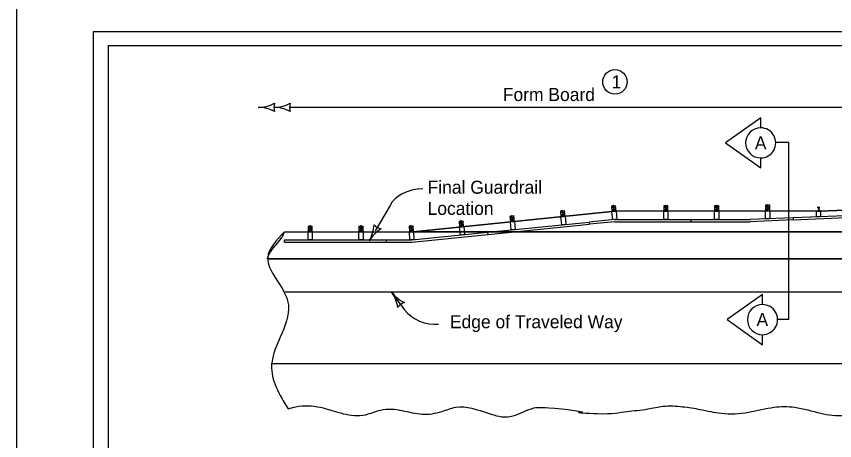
# Model space of a CAD drawing. Extents: x 10038 to 81668, y 7924 to 11018.
# Drawn here: x 10038 to 11041, y 9442 to 9962 of the extents above; entities that cross this region are included whole.
import ezdxf

# ---------------------------------------------------------------- set-up
doc = ezdxf.new("R2010")
doc.units = 0
for name, color, linetype in [('dsnCellElements', 7, 'Continuous'), ('DsnShtMinorGrid05', 7, 'Continuous'), ('DsnShtMinorGrid06', 7, 'Continuous'), ('DsnShtMinorGrid07', 7, 'Continuous'), ('DsnShtMinorGrid09', 7, 'Continuous'), ('DsnShtMinorGrid10', 7, 'Continuous'), ('DsnShtMinorGrid11', 7, 'Continuous'), ('DsnShtMinorGrid13', 7, 'Continuous'), ('DsnShtMinorGrid14', 7, 'Continuous'), ('Level 60', 7, 'Continuous'), ('SheetBorder', 7, 'Continuous')]:
    doc.layers.add(name, color=color, linetype=linetype)

msp = doc.modelspace()

# ---------------------------------------------------------------- linework, layer by layer
at = {"layer": 'dsnCellElements'}
msp.add_lwpolyline([(10037.7, 8180), (13358.6, 8180), (13358.6, 10373.4), (10037.7, 10373.4)], close=True, dxfattribs=at)
at = {"layer": 'DsnShtMinorGrid05'}
msp.add_line((10373.6, 9850.8), (11396, 9850.8), dxfattribs=at)
for centre, radius, start, end in [((10334.4, 9893.2), 42.5, 270, 298.0725), ((10334.4, 9808.2), 42.5, 61.9275, 90), ((10353.6, 9893.2), 42.5, 270, 298.0725), ((10370, 9850.7), 16.4, 162.2666, 197.7334), ((10353.6, 9808.2), 42.5, 61.9275, 90), ((10389.2, 9850.7), 16.4, 162.2666, 197.7334)]:
    msp.add_arc(centre, radius, start, end, dxfattribs=at)
at = {"layer": 'DsnShtMinorGrid06'}
for q in [(10150.3, 8316.7), (13246, 9926.7)]:
    msp.add_line((10150.3, 9926.7), q, dxfattribs=at)
at = {"layer": 'DsnShtMinorGrid07'}
for p, q in [((11023.5, 9728), (11020.2, 9728)), ((11020.2, 9728), (11020.2, 9727.8)), ((11020.2, 9728), (11020.2, 9727.8)), ((11023.5, 9728), (11020.2, 9728)), ((11020.2, 9727.8), (11021.3, 9727.8)), ((11020.2, 9727.8), (11021.3, 9727.8)), ((11021.8, 9727.4), (11021.8, 9723.6)), ((11021.8, 9727.4), (11021.8, 9723.6)), ((11021.9, 9723.6), (11021.9, 9727.4)), ((11021.9, 9723.6), (11021.9, 9727.4)), ((11022.3, 9727.8), (11023.5, 9727.8)), ((11022.3, 9727.8), (11023.5, 9727.8)), ((11023.5, 9727.8), (11023.5, 9728)), ((11023.5, 9727.8), (11023.5, 9728)), ((11019.2, 9716.4), (11019.2, 9723.4)), ((11019.2, 9723.4), (11019.9, 9723.4)), ((11019.9, 9723.1), (11019.9, 9723.4)), ((11023.6, 9723.1), (11019.9, 9723.1)), ((11021.3, 9723.2), (11020.2, 9723.2)), ((11020.2, 9723.2), (11020.2, 9723.1)), ((11020.2, 9723.2), (11020.2, 9723.1)), ((11021.3, 9723.2), (11020.2, 9723.2)), ((11020.2, 9723.1), (11023.5, 9723.1)), ((11020.2, 9723.1), (11023.5, 9723.1)), ((11022.1, 9723.7), (11022.1, 9723.3)), ((11022.1, 9723.3), (11022.1, 9723.7)), ((11022.2, 9723.7), (11022.1, 9723.7)), ((11022.2, 9723.7), (11022.1, 9723.7)), ((11022.2, 9723.7), (11023.1, 9723.7)), ((11023.1, 9723.7), (11022.2, 9723.7)), ((11023.5, 9723.2), (11022.3, 9723.2)), ((11023.5, 9723.2), (11022.3, 9723.2)), ((11022.9, 9725.2), (11022.4, 9725.2)), ((11022.4, 9725.2), (11022.4, 9723.7)), ((11022.9, 9725.2), (11022.4, 9725.2)), ((11022.4, 9725.2), (11022.4, 9723.7)), ((11022.4, 9723.7), (11022.9, 9723.7)), ((11022.4, 9723.7), (11022.4, 9723.3)), ((11022.4, 9723.3), (11022.4, 9723.7)), ((11022.4, 9723.3), (11022.4, 9723.7)), ((11022.9, 9723.7), (11022.9, 9725.2)), ((11022.9, 9723.7), (11022.9, 9725.2)), ((11023, 9723.3), (11023, 9723.7)), ((11023, 9723.7), (11023, 9723.3)), ((11023, 9723.3), (11023, 9723.7)), ((11023.1, 9723.7), (11023.2, 9723.7)), ((11023.2, 9723.7), (11023.1, 9723.7)), ((11023.3, 9723.7), (11023.2, 9723.7)), ((11023.3, 9723.7), (11023.2, 9723.7)), ((11023.2, 9723.2), (11023.3, 9723.3)), ((11023.2, 9723.2), (11023.3, 9723.3)), ((11023.3, 9723.3), (11023.3, 9723.7)), ((11023.3, 9723.3), (11023.3, 9723.7)), ((11023.5, 9723.1), (11023.5, 9723.2)), ((11023.5, 9723.1), (11023.5, 9723.2)), ((11023.6, 9723.4), (11024.2, 9723.4)), ((11023.6, 9723.4), (11023.6, 9723.1)), ((11024.2, 9723.4), (11024.2, 9716.4)), ((11024.2, 9716.4), (11019.2, 9716.4))]:
    msp.add_line(p, q, dxfattribs=at)
for points in [[(11022.1, 9723.3), (11022.1, 9723.3)], [(11022.3, 9723.2), (11023.2, 9723.2), (11023.2, 9723.2)]]:
    msp.add_lwpolyline(points, dxfattribs=at)
for centre, start, end in [((11021.3, 9727.4), 359.9934, 90.0025), ((11021.3, 9727.4), 359.9934, 90.0025), ((11022.3, 9727.4), 90.0073, 179.9964), ((11022.3, 9727.4), 90.0073, 179.9964), ((11021.3, 9723.6), 270.0073, 359.9964), ((11021.3, 9723.6), 270.0073, 359.9964), ((11022.3, 9723.6), 179.9934, 270.0025), ((11022.3, 9723.6), 179.9934, 270.0025), ((11022.3, 9723.6), 230.8866, 270.0025)]:
    msp.add_arc(centre, 0.417, start, end, dxfattribs=at)
for points in [[(11022.4, 9723.7), (11022.3, 9723.7), (11022.3, 9723.7), (11022.2, 9723.7), (11022.1, 9723.7), (11022.1, 9723.7), (11022.1, 9723.7)], [(11022.4, 9723.7), (11022.3, 9723.7), (11022.3, 9723.7), (11022.2, 9723.7), (11022.1, 9723.7), (11022.1, 9723.7), (11022.1, 9723.7)], [(11022.1, 9723.7), (11022.1, 9723.7), (11022.1, 9723.7), (11022.2, 9723.7), (11022.3, 9723.7), (11022.3, 9723.7), (11022.4, 9723.7)], [(11022.3, 9723.2), (11022.3, 9723.2), (11022.3, 9723.2), (11022.3, 9723.2), (11022.4, 9723.3)], [(11023, 9723.7), (11022.9, 9723.7), (11022.8, 9723.7), (11022.7, 9723.7), (11022.5, 9723.7), (11022.4, 9723.7), (11022.4, 9723.7)], [(11023, 9723.7), (11022.9, 9723.7), (11022.8, 9723.7), (11022.7, 9723.7), (11022.5, 9723.7), (11022.4, 9723.7), (11022.4, 9723.7)], [(11022.4, 9723.7), (11022.4, 9723.7), (11022.5, 9723.7), (11022.7, 9723.7), (11022.8, 9723.7), (11022.9, 9723.7), (11023, 9723.7)], [(11022.4, 9723.3), (11022.4, 9723.2), (11022.5, 9723.2), (11022.7, 9723.2), (11022.8, 9723.2), (11022.9, 9723.2), (11023, 9723.3)], [(11023, 9723.3), (11022.9, 9723.2), (11022.8, 9723.2), (11022.7, 9723.2), (11022.5, 9723.2), (11022.4, 9723.2), (11022.4, 9723.3)], [(11022.4, 9723.3), (11022.4, 9723.2), (11022.5, 9723.2), (11022.7, 9723.2), (11022.8, 9723.2), (11022.9, 9723.2), (11023, 9723.3)], [(11023.3, 9723.7), (11023.3, 9723.7), (11023.2, 9723.7), (11023.2, 9723.7), (11023.1, 9723.7), (11023, 9723.7), (11023, 9723.7), (11023, 9723.7)], [(11023.3, 9723.7), (11023.3, 9723.7), (11023.2, 9723.7), (11023.2, 9723.7), (11023.1, 9723.7), (11023, 9723.7), (11023, 9723.7), (11023, 9723.7)], [(11023, 9723.7), (11023, 9723.7), (11023, 9723.7), (11023.1, 9723.7), (11023.2, 9723.7), (11023.2, 9723.7), (11023.3, 9723.7), (11023.3, 9723.7)], [(11023, 9723.3), (11023, 9723.3), (11023, 9723.2), (11023.1, 9723.2), (11023.2, 9723.2), (11023.2, 9723.2), (11023.3, 9723.3), (11023.3, 9723.3)], [(11023.3, 9723.3), (11023.3, 9723.3), (11023.2, 9723.2), (11023.2, 9723.2), (11023.1, 9723.2), (11023, 9723.2), (11023, 9723.3), (11023, 9723.3)], [(11023, 9723.3), (11023, 9723.3), (11023, 9723.2), (11023.1, 9723.2), (11023.2, 9723.2), (11023.2, 9723.2), (11023.3, 9723.3), (11023.3, 9723.3)]]:
    msp.add_open_spline(points, degree=3, dxfattribs=at)
at = {"layer": 'DsnShtMinorGrid09'}
msp.add_circle((10772, 9882), 15, dxfattribs=at)
at = {"layer": 'DsnShtMinorGrid10'}
for p, q in [((10496.3, 9730.4), (10477.8, 9699)), ((10509.9, 9607.9), (10497.8, 9624.3)), ((10550, 9584.8), (10555.5, 9584.8))]:
    msp.add_line(p, q, dxfattribs=at)
for centre, radius, start, end in [((10434, 9708.5), 42.5, 329.3797, 357.4522), ((10488.7, 9717.5), 16.4, 221.6464, 257.1131), ((10507.1, 9665.2), 42.5, 121.3072, 149.3797), ((10532, 9649.6), 42.5, 216.3726, 244.445), ((10463.6, 9599.1), 42.5, 8.3001, 36.3726), ((10518.9, 9595.7), 16.4, 108.6392, 144.1059), ((10550.1, 9631.3), 46.5, 210.2274, 270)]:
    msp.add_arc(centre, radius, start, end, dxfattribs=at)
msp.add_ellipse((10577.4, 9691.3), major_axis=(-81.1, 39), ratio=0.555556, start_param=5.482641, end_param=6.283185, dxfattribs=at)
at = {"layer": 'DsnShtMinorGrid11'}
for p, q in [((11452.4, 9740.7), (11023.5, 9723.1)), ((10772.3, 9723.1), (10524.5, 9698)), ((11023.5, 9723.1), (10772.3, 9723.1)), ((10524.5, 9698), (11498.9, 9698)), ((11556.5, 9698), (10524.5, 9698)), ((10350.4, 9536.4), (11992.4, 9536.4))]:
    msp.add_line(p, q, dxfattribs=at)
at = {"layer": 'DsnShtMinorGrid13'}
for p, q in [((10985.4, 9807.4), (10969.6, 9807.4)), ((10985.4, 9590.2), (10985.4, 9807.4)), ((10985.4, 9590.2), (10971.5, 9590.2))]:
    msp.add_line(p, q, dxfattribs=at)
for points in [[(10950.8, 9825.6), (10950.8, 9838), (10907.7, 9807.1), (10950.8, 9776.3), (10950.8, 9788.7)], [(10953, 9608.6), (10953, 9621), (10909.8, 9590.2), (10953, 9559.4), (10953, 9571.7)]]:
    msp.add_lwpolyline(points, dxfattribs=at)
for centre, start, end in [((10950.8, 9807.1), 90.0008, 269.9992), ((10950.8, 9807.1), 269.9992, 90.0008), ((10953, 9590.2), 90.0008, 269.9992), ((10953, 9590.2), 269.9992, 90.0008)]:
    msp.add_arc(centre, 18.5, start, end, dxfattribs=at)
at = {"layer": 'DsnShtMinorGrid14'}
for p, q in [((10767.6, 9729.4), (10773.3, 9723.3)), ((10772.6, 9729.9), (10768.3, 9722.8)), ((10770, 9730.6), (10770, 9730.7)), ((10770.8, 9723), (10770.1, 9729.6)), ((10831.8, 9729.7), (10836.8, 9723.1)), ((10836.8, 9729.7), (10831.8, 9723.1)), ((10834.3, 9730.7), (10834.3, 9730.8)), ((10834.3, 9723.1), (10834.3, 9729.7)), ((10894.3, 9729.7), (10899.3, 9723.1)), ((10899.3, 9729.7), (10894.3, 9723.1)), ((10896.8, 9730.7), (10896.8, 9730.8)), ((10896.8, 9723.1), (10896.8, 9729.7)), ((10956.8, 9730.6), (10961.8, 9723.9)), ((10961.8, 9730.6), (10956.8, 9723.9)), ((10959.3, 9731.6), (10959.3, 9731.6)), ((10959.3, 9723.9), (10959.3, 9730.6)), ((10643, 9716.9), (10648.6, 9710.7)), ((10648, 9717.4), (10643.7, 9710.2)), ((10645.4, 9718.1), (10645.4, 9718.1)), ((10646.1, 9710.5), (10645.5, 9717.1)), ((10705.2, 9723.1), (10710.8, 9717)), ((10710.1, 9723.6), (10705.8, 9716.5)), ((10705.8, 9716.5), (10710.8, 9717)), ((10706.8, 9706.5), (10705.8, 9716.5)), ((10707.6, 9724.3), (10707.6, 9724.4)), ((10708.3, 9716.7), (10707.7, 9723.4)), ((10710.8, 9717), (10711.8, 9707)), ((10768.3, 9722.8), (10773.3, 9723.3)), ((10770.8, 9723), (10768.3, 9722.8)), ((10770.8, 9723), (10768.3, 9722.8)), ((10769.3, 9712.8), (10768.3, 9722.8)), ((10773.3, 9723.3), (10774.3, 9713.3)), ((10831.8, 9723.1), (10836.8, 9723.1)), ((10831.8, 9713), (10831.8, 9723.1)), ((10836.8, 9723.1), (10836.8, 9713)), ((10894.3, 9723.1), (10899.3, 9723.1)), ((10894.3, 9713), (10894.3, 9723.1)), ((10899.3, 9723.1), (10899.3, 9713)), ((10956.8, 9723.9), (10961.8, 9723.9)), ((10956.8, 9713.9), (10956.8, 9723.9)), ((10961.8, 9723.9), (10961.8, 9713.9)), ((10580.8, 9710.6), (10586.4, 9704.5)), ((10585.8, 9711.1), (10581.5, 9704)), ((10583.2, 9711.9), (10583.2, 9711.9)), ((10584, 9704.2), (10583.3, 9710.9)), ((10616.1, 9697.4), (10740.4, 9709.9)), ((10616.3, 9694.7), (10740.7, 9707.2)), ((10643.7, 9710.2), (10648.6, 9710.7)), ((10644.7, 9700.3), (10643.7, 9710.2)), ((10648.6, 9710.7), (10649.6, 9700.8)), ((10711.8, 9707), (10706.8, 9706.5)), ((10771.8, 9713), (10740.4, 9709.9)), ((10740.7, 9707.2), (10740.4, 9709.9)), ((10740.7, 9707.2), (10740.4, 9709.9)), ((10771.8, 9710.3), (10740.7, 9707.2)), ((10774.3, 9713.3), (10769.3, 9712.8)), ((10771.8, 9713), (10865.5, 9713)), ((10771.8, 9710.3), (10865.5, 9710.3)), ((10836.8, 9713), (10831.8, 9713)), ((10865.5, 9710.3), (10865.5, 9713)), ((10865.5, 9713), (10937.8, 9713)), ((10865.5, 9710.3), (10865.5, 9713)), ((10865.5, 9710.3), (10937.8, 9710.3)), ((10899.3, 9713), (10894.3, 9713)), ((10961.8, 9713.9), (10956.8, 9713.9)), ((10395.5, 9704.6), (10400.5, 9698)), ((10400.5, 9704.6), (10395.5, 9698)), ((10395.5, 9698), (10400.5, 9698)), ((10395.5, 9688), (10395.5, 9698)), ((10398, 9705.6), (10398, 9705.7)), ((10398, 9698), (10398, 9704.6)), ((10400.5, 9698), (10400.5, 9688)), ((10458, 9704.6), (10463, 9698)), ((10463, 9704.6), (10458, 9698)), ((10458, 9698), (10463, 9698)), ((10458, 9688), (10458, 9698)), ((10460.5, 9705.6), (10460.5, 9705.7)), ((10460.5, 9698), (10460.5, 9704.6)), ((10463, 9698), (10463, 9688)), ((10519.4, 9704.7), (10524.8, 9698.3)), ((10524.4, 9705), (10519.8, 9698)), ((10519.8, 9698), (10524.8, 9698.3)), ((10520.3, 9688), (10519.8, 9698)), ((10521.9, 9705.8), (10521.9, 9705.9)), ((10522.3, 9698.1), (10521.9, 9704.8)), ((10522.8, 9688), (10616.1, 9697.4)), ((10524.8, 9698.3), (10525.3, 9688.2)), ((10581.5, 9704), (10586.5, 9704.5)), ((10582.5, 9694), (10581.5, 9704)), ((10586.5, 9704.5), (10587.4, 9694.5)), ((10616.3, 9694.7), (10616.1, 9697.4)), ((10616.3, 9694.7), (10616.1, 9697.4)), ((10649.6, 9700.8), (10644.7, 9700.3)), ((10366.8, 9688), (10491.8, 9688)), ((10366.8, 9685.3), (10366.8, 9688)), ((10400.5, 9688), (10395.5, 9688)), ((10463, 9688), (10458, 9688)), ((10491.8, 9688), (10522.8, 9688)), ((10491.8, 9685.3), (10491.8, 9688)), ((10525.3, 9688.2), (10520.3, 9688)), ((10523, 9685.3), (10616.3, 9694.7)), ((10587.4, 9694.5), (10582.5, 9694)), ((10366.8, 9685.3), (10491.8, 9685.3)), ((10491.8, 9685.3), (10523, 9685.3))]:
    msp.add_line(p, q, dxfattribs=at)
for points in [[(10768.3, 9722.8), (10773.3, 9723.3), (10772.6, 9729.9), (10767.6, 9729.4)], [(10831.8, 9723.1), (10836.8, 9723.1), (10836.8, 9729.7), (10831.8, 9729.7)], [(10894.3, 9723.1), (10899.3, 9723.1), (10899.3, 9729.7), (10894.3, 9729.7)], [(10956.8, 9723.9), (10961.8, 9723.9), (10961.8, 9730.6), (10956.8, 9730.6)], [(10643.7, 9710.2), (10648.6, 9710.7), (10648, 9717.4), (10643, 9716.9)], [(10705.8, 9716.5), (10710.8, 9717), (10710.1, 9723.6), (10705.2, 9723.1)], [(10581.5, 9704), (10586.4, 9704.5), (10585.8, 9711.1), (10580.8, 9710.6)], [(10395.5, 9698), (10400.5, 9698), (10400.5, 9704.6), (10395.5, 9704.6)], [(10458, 9698), (10463, 9698), (10463, 9704.6), (10458, 9704.6)], [(10519.8, 9698), (10524.8, 9698.3), (10524.4, 9705), (10519.4, 9704.7)]]:
    msp.add_lwpolyline(points, close=True, dxfattribs=at)
for points in [[(10769.9, 9730), (10769.8, 9730.6), (10770.2, 9730.6), (10770.3, 9730.1)], [(10769.8, 9729.6), (10769.8, 9730), (10770.4, 9730.1), (10770.5, 9729.7)], [(10834, 9729.7), (10834, 9730.2), (10834.6, 9730.2), (10834.6, 9729.7)], [(10834.1, 9730.2), (10834.1, 9730.7), (10834.5, 9730.7), (10834.5, 9730.2)], [(10896.5, 9729.7), (10896.5, 9730.2), (10897.1, 9730.2), (10897.1, 9729.7)], [(10896.6, 9730.2), (10896.6, 9730.7), (10897, 9730.7), (10897, 9730.2)], [(10959, 9730.6), (10959, 9731), (10959.6, 9731), (10959.6, 9730.6)], [(10959.1, 9731), (10959.1, 9731.6), (10959.5, 9731.6), (10959.5, 9731)], [(10645.1, 9717.1), (10645.1, 9717.5), (10645.8, 9717.6), (10645.8, 9717.1)], [(10645.2, 9717.5), (10645.2, 9718.1), (10645.6, 9718.1), (10645.6, 9717.6)], [(10707.3, 9723.3), (10707.3, 9723.8), (10708, 9723.8), (10708, 9723.4)], [(10707.4, 9723.8), (10707.4, 9724.3), (10707.8, 9724.3), (10707.8, 9723.8)], [(10583, 9710.9), (10582.9, 9711.3), (10583.6, 9711.4), (10583.6, 9710.9)], [(10583.1, 9711.3), (10583, 9711.9), (10583.4, 9711.9), (10583.4, 9711.3)], [(10397.7, 9704.6), (10397.7, 9705.1), (10398.4, 9705.1), (10398.4, 9704.6)], [(10397.8, 9705.1), (10397.8, 9705.6), (10398.2, 9705.6), (10398.2, 9705.1)], [(10460.2, 9704.6), (10460.2, 9705.1), (10460.9, 9705.1), (10460.9, 9704.6)], [(10460.3, 9705.1), (10460.3, 9705.6), (10460.7, 9705.6), (10460.7, 9705.1)], [(10522.3, 9698.1), (10519.8, 9698), (10519.8, 9698)], [(10521.6, 9704.8), (10521.6, 9705.3), (10522.2, 9705.3), (10522.3, 9704.9)], [(10521.7, 9705.3), (10521.7, 9705.8), (10522.1, 9705.8), (10522.1, 9705.3)]]:
    msp.add_lwpolyline(points, dxfattribs=at)
at = {"layer": 'Level 60'}
for p, q in [((11023.5, 9723.1), (11498.9, 9742.6)), ((11402.1, 9731.6), (10990.5, 9715.2)), ((11402.2, 9728.9), (10990.5, 9712.4)), ((11020.2, 9728), (11020.2, 9727.8)), ((11023.5, 9728), (11020.2, 9728)), ((11020.2, 9727.8), (11021.3, 9727.8)), ((11021.8, 9727.4), (11021.8, 9723.6)), ((11021.9, 9723.6), (11021.9, 9727.4)), ((11022.3, 9727.8), (11023.5, 9727.8)), ((11023.5, 9727.8), (11023.5, 9728)), ((10524.5, 9698), (10772.3, 9723.1)), ((11020.2, 9723.1), (10772.3, 9723.1)), ((11019.2, 9716.4), (11019.2, 9723.4)), ((11019.2, 9723.4), (11019.9, 9723.4)), ((11019.9, 9723.1), (11019.9, 9723.4)), ((11023.6, 9723.1), (11019.9, 9723.1)), ((11020.2, 9723.2), (11020.2, 9723.1)), ((11021.3, 9723.2), (11020.2, 9723.2)), ((11020.2, 9723.1), (11023.5, 9723.1)), ((11022.1, 9723.3), (11022.1, 9723.7)), ((11022.2, 9723.7), (11022.1, 9723.7)), ((11022.2, 9723.7), (11023.1, 9723.7)), ((11023.5, 9723.2), (11022.3, 9723.2)), ((11022.9, 9725.2), (11022.4, 9725.2)), ((11022.4, 9725.2), (11022.4, 9723.7)), ((11022.4, 9723.3), (11022.4, 9723.7)), ((11022.9, 9723.7), (11022.9, 9725.2)), ((11023, 9723.3), (11023, 9723.7)), ((11023.1, 9723.7), (11023.2, 9723.7)), ((11023.3, 9723.7), (11023.2, 9723.7)), ((11023.2, 9723.2), (11023.3, 9723.3)), ((11023.3, 9723.3), (11023.3, 9723.7)), ((11023.5, 9723.1), (11023.5, 9723.2)), ((11023.6, 9723.4), (11024.2, 9723.4)), ((11023.6, 9723.4), (11023.6, 9723.1)), ((11024.2, 9723.4), (11024.2, 9716.4)), ((10990.5, 9715.2), (10937.8, 9713)), ((10990.6, 9712.5), (10937.8, 9710.3)), ((10990.5, 9715.2), (10990.6, 9712.5)), ((10990.5, 9715.2), (10990.6, 9712.5)), ((11024.2, 9716.4), (11019.2, 9716.4)), ((10366.8, 9698), (10524.5, 9698)), ((10366.8, 9698), (11498.9, 9698)), ((10345.8, 9665), (11993.3, 9665)), ((11498.9, 9665), (10345.8, 9665)), ((10367, 9624.3), (11980.8, 9624.3))]:
    msp.add_line(p, q, dxfattribs=at)
for centre, start, end in [((11021.3, 9727.4), 359.9934, 90.0025), ((11022.3, 9727.4), 90.0073, 179.9964), ((11021.3, 9723.6), 270.0073, 359.9964), ((11022.3, 9723.6), 264.7174, 270.0025)]:
    msp.add_arc(centre, 0.417, start, end, dxfattribs=at)
for points in [[(11022.4, 9723.7), (11022.3, 9723.7), (11022.3, 9723.7), (11022.2, 9723.7), (11022.1, 9723.7), (11022.1, 9723.7), (11022.1, 9723.7)], [(11022.3, 9723.2), (11022.3, 9723.2), (11022.3, 9723.2), (11022.3, 9723.2), (11022.4, 9723.3)], [(11023, 9723.7), (11022.9, 9723.7), (11022.8, 9723.7), (11022.7, 9723.7), (11022.5, 9723.7), (11022.4, 9723.7), (11022.4, 9723.7)], [(11022.4, 9723.3), (11022.4, 9723.2), (11022.5, 9723.2), (11022.7, 9723.2), (11022.8, 9723.2), (11022.9, 9723.2), (11023, 9723.3)], [(11023.3, 9723.7), (11023.3, 9723.7), (11023.2, 9723.7), (11023.2, 9723.7), (11023.1, 9723.7), (11023, 9723.7), (11023, 9723.7), (11023, 9723.7)], [(11023, 9723.3), (11023, 9723.3), (11023, 9723.2), (11023.1, 9723.2), (11023.2, 9723.2), (11023.2, 9723.2), (11023.3, 9723.3), (11023.3, 9723.3)]]:
    msp.add_open_spline(points, degree=3, dxfattribs=at)
for points in [[(10366.8, 9698), (10346.1, 9666.4), (10370.5, 9613.3), (10350.8, 9534.2), (10371.1, 9480.6)], [(10345.8, 9665), (10346.1, 9666.4), (10347.8, 9670.5), (10350.2, 9674.4), (10356.3, 9682), (10362.4, 9689.7), (10366, 9695.8), (10366.8, 9698)], [(10371.1, 9480.6), (10380.5, 9483.2), (10410.7, 9482.6), (10438.7, 9474.7), (10466, 9473.5), (10484.3, 9479.2), (10511.1, 9478.6), (10535.6, 9474.1), (10559.6, 9477.5), (10576.7, 9482.6), (10616.6, 9475.2), (10643.4, 9471.2), (10667.9, 9480.4), (10690.7, 9482.1), (10729.5, 9476.4), (10728.9, 9476.4), (10750.1, 9474.8), (10787.1, 9477.6), (10812.2, 9480.5), (10831, 9483.9), (10855, 9483.3), (10876.7, 9479.9), (10902.3, 9475.3), (10936, 9476.5), (10967.3, 9482.7), (10992.4, 9482.7), (11024.4, 9475.3), (11053.4, 9472.5), (11087.1, 9479.3), (11119.6, 9482.7), (11153.8, 9475.9), (11179.5, 9473), (11201.7, 9476.5), (11229.6, 9491.9), (11239.9, 9494.2), (11264.4, 9496.4), (11295.1, 9497), (11316.2, 9497), (11369.5, 9487.7)]]:
    msp.add_spline(points, degree=3, dxfattribs=at)
at = {"layer": 'SheetBorder'}
msp.add_lwpolyline([(10132.5, 9944), (13267.5, 9944), (13267.5, 7924), (10132.5, 7924)], close=True, dxfattribs=at)

# ---------------------------------------------------------------- texts
at = {"layer": 'DsnShtMinorGrid05'}
msp.add_text('Form Board', height=16, dxfattribs=at).set_placement((10634.5, 9858.5))
at = {"layer": 'DsnShtMinorGrid09'}
msp.add_text('1', height=16, dxfattribs=at).set_placement((10767.9, 9874))
at = {"layer": 'DsnShtMinorGrid10'}
for s, p in [('Final Guardrail ', (10542.2, 9744.7)), ('Location', (10542.2, 9718.7)), ('Edge of Traveled Way', (10569.6, 9579.6))]:
    msp.add_text(s, height=16, dxfattribs=at).set_placement(p)
at = {"layer": 'DsnShtMinorGrid13'}
for p in [(10943.6, 9799.1), (10945.7, 9582.2)]:
    msp.add_text('A', height=16, dxfattribs=at).set_placement(p)

doc.saveas('drawing.dxf')
